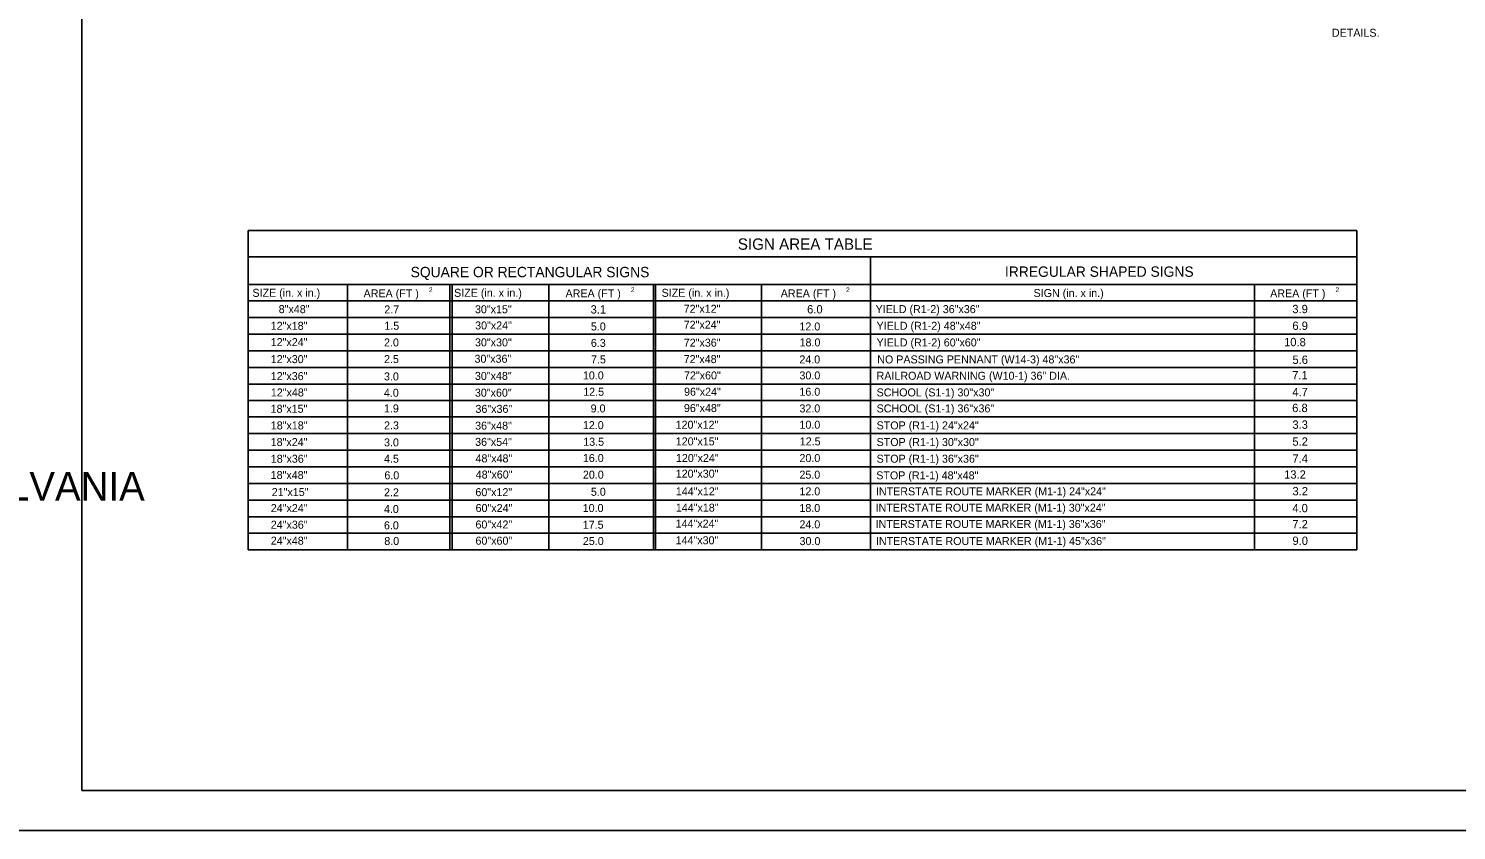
# Model space of a CAD drawing. Extents: x 644358 to 648627, y 294594 to 295782.
# Drawn here: x 645219 to 645755, y 294594 to 294894 of the extents above; entities that cross this region are included whole.
import ezdxf

# ---------------------------------------------------------------- set-up
doc = ezdxf.new("R2010")
doc.units = 0
for name, color, linetype in [('1', 7, 'Continuous'), ('2', 7, 'Continuous'), ('3', 7, 'Continuous'), ('4', 7, 'Continuous'), ('PLT-BNDY', 7, 'Continuous')]:
    doc.layers.add(name, color=color, linetype=linetype)

msp = doc.modelspace()

# ---------------------------------------------------------------- linework, layer by layer
at = {"layer": '1'}
for p, q in [((645239.31, 295172.63), (645239.31, 294608.63)), ((646025.31, 294608.63), (645239.31, 294608.63)), ((645239.31, 294608.63), (645825.31, 294608.63))]:
    msp.add_line(p, q, dxfattribs=at)
at = {"layer": '2'}
for p, q in [((645301.64, 294818.71), (645301.64, 294698.96)), ((645717.39, 294818.71), (645301.64, 294818.71)), ((645717.39, 294698.96), (645717.39, 294818.71)), ((645717.39, 294808.84), (645301.64, 294808.84)), ((645535.01, 294808.84), (645535.01, 294698.96)), ((645301.64, 294798.46), (645717.39, 294798.46)), ((645338.89, 294798.46), (645338.89, 294698.96)), ((645377.26, 294798.46), (645377.26, 294698.96)), ((645378.14, 294798.46), (645378.14, 294698.96)), ((645414.43, 294798.46), (645414.43, 294698.96)), ((645453.64, 294798.46), (645453.64, 294698.96)), ((645454.39, 294798.46), (645454.39, 294698.96)), ((645494.14, 294798.46), (645494.14, 294698.96)), ((645679.01, 294698.96), (645679.01, 294798.46)), ((645301.64, 294792.34), (645717.39, 294792.34)), ((645301.64, 294786.09), (645717.39, 294786.09)), ((645301.64, 294779.84), (645717.39, 294779.84)), ((645301.64, 294773.59), (645717.39, 294773.59)), ((645301.64, 294767.34), (645717.39, 294767.34)), ((645301.64, 294761.09), (645717.39, 294761.09)), ((645301.64, 294754.96), (645717.39, 294754.96)), ((645301.64, 294748.84), (645717.39, 294748.84)), ((645301.64, 294742.59), (645717.39, 294742.59)), ((645301.64, 294736.34), (645717.39, 294736.34)), ((645301.64, 294730.09), (645717.39, 294730.09)), ((645301.64, 294723.84), (645717.39, 294723.84)), ((645301.64, 294717.59), (645717.39, 294717.59)), ((645535.01, 294717.59), (645717.39, 294717.59)), ((645301.64, 294711.34), (645717.39, 294711.34)), ((645717.39, 294711.34), (645535.01, 294711.34)), ((645301.64, 294705.21), (645717.39, 294705.21)), ((645301.64, 294698.96), (645535.01, 294698.96)), ((645717.39, 294698.96), (645535.01, 294698.96))]:
    msp.add_line(p, q, dxfattribs=at)
at = {"layer": '4'}
for p, q in [((645356.09, 294712.84), (645356.09, 294712.84)), ((645356.09, 294706.59), (645356.09, 294706.59)), ((645356.09, 294700.34), (645356.09, 294700.34))]:
    msp.add_line(p, q, dxfattribs=at)
at = {"layer": 'PLT-BNDY'}
msp.add_lwpolyline([(645199.31, 295187.63), (646040.31, 295187.63), (646040.31, 294593.63), (645199.31, 294593.63)], close=True, dxfattribs=at)

# ---------------------------------------------------------------- texts
at = {"layer": '1'}
msp.add_text('COMMONWEALTH OF PENNSYLVANIA', height=10.7828, dxfattribs=at).set_placement((644996.9, 294717.36))
at = {"layer": '3'}
msp.add_text('DETAILS.', height=3, dxfattribs=at).set_placement((645708.03, 294891.41))
at = {"layer": '4'}
for s, height, p in [('SIGN AREA TABLE', 4.25, (645485.26, 294811.5)), ('SQUARE OR RECTANGULAR SIGNS', 3.8872, (645362.56, 294801.19)), ('IRREGULAR SHAPED SIGNS', 3.8872, (645585.41, 294801.34)), ('2', 1.8, (645369.42, 294795.6)), ('2', 1.8, (645445.15, 294795.6)), ('2', 1.8, (645525.85, 294795.6)), ('2', 1.8, (645709.36, 294795.6)), ('SIZE (in. x in.)', 3, (645303.26, 294793.84)), ('AREA (FT )', 3, (645344.93, 294793.63)), ('SIZE (in. x in.)', 3, (645378.87, 294793.84)), ('AREA (FT )', 3, (645420.66, 294793.63)), ('SIZE (in. x in.)', 3, (645456.69, 294793.84)), ('AREA (FT )', 3, (645501.36, 294793.63)), ('SIGN (in. x in.)', 3, (645596.15, 294793.76)), ('AREA (FT )', 3, (645684.87, 294793.63)), ('8"x48"', 3, (645313.11, 294787.71)), ('2.7', 3, (645352.7, 294787.6)), ('30"x15"', 3, (645386.7, 294787.67)), ('3.1', 3.125, (645430.06, 294787.55)), ('72"x12"', 3, (645464.95, 294787.85)), ('6.0', 3.125, (645511.25, 294787.6)), ('YIELD (R1-2) 36"x36" ', 3, (645536.92, 294787.72)), ('3.9', 3.125, (645693.18, 294787.71)), ('12"x18"', 3, (645310.11, 294781.46)), ('1.5', 3, (645352.73, 294781.49)), ('30"x24"', 3, (645386.76, 294781.6)), ('5.0', 3, (645430.16, 294781.22)), ('72"x24"', 3, (645464.97, 294781.88)), ('12.0', 3, (645508.36, 294781.22)), ('YIELD (R1-2) 48"x48" ', 3, (645537.29, 294781.47)), ('6.9', 3.125, (645693.21, 294781.42)), ('12"x24"', 3, (645310.11, 294775.34)), ('2.0', 3, (645352.6, 294775.22)), ('30"x30"', 3, (645386.71, 294775.25)), ('6.3', 3, (645430.16, 294775.05)), ('72"x36"', 3, (645464.99, 294775.14)), ('18.0', 3, (645508.41, 294775.23)), ('YIELD (R1-2) 60"x60" ', 3, (645537.29, 294775.22)), ('10.8', 3.125, (645690.09, 294775.3)), ('12"x30"', 3, (645310.11, 294768.96)), ('2.5', 3, (645352.6, 294768.98)), ('30"x36"', 3, (645386.53, 294769.1)), ('7.5', 3, (645430.2, 294768.85)), ('72"x48"', 3, (645464.96, 294768.97)), ('24.0', 3, (645508.32, 294768.85)), ('NO PASSING PENNANT (W14-3) 48"x36" ', 3, (645537.54, 294768.85)), ('5.6', 3.125, (645693.23, 294768.67)), ('12"x36"', 3, (645310.11, 294762.59)), ('3.0', 3, (645352.59, 294762.47)), ('30"x48"', 3, (645386.68, 294762.67)), ('10.0', 3, (645427.17, 294762.85)), ('72"x60"', 3, (645465.08, 294762.85)), ('30.0', 3, (645508.37, 294762.85)), ('RAILROAD WARNING (W10-1) 36" DIA.', 3, (645537.29, 294762.72)), ('7.1', 3.125, (645693.13, 294762.86)), ('12.5', 3, (645427.29, 294756.72)), ('96"x24"', 3, (645465.1, 294756.73)), ('16.0', 3, (645508.36, 294756.72)), ('SCHOOL (S1-1) 30"x30" ', 3, (645537.29, 294756.47)), ('4.7', 3.125, (645693.18, 294756.56)), ('12"x48"', 3, (645310.16, 294756.46)), ('4.0', 3, (645352.55, 294756.34)), ('30"x60"', 3, (645386.68, 294756.37)), ('18"x15"', 3, (645310.08, 294750.34)), ('1.9', 3, (645352.58, 294750.47)), ('36"x36"', 3, (645386.88, 294750.3)), ('9.0', 3, (645430.07, 294750.47)), ('96"x48"', 3, (645465.05, 294750.61)), ('32.0', 3, (645508.36, 294750.47)), ('SCHOOL (S1-1) 36"x36" ', 3, (645537.29, 294750.47)), ('6.8', 3.125, (645693.12, 294750.6)), ('18"x18"', 3, (645310.14, 294744.09)), ('2.3', 3, (645352.6, 294744.1)), ('36"x48"', 3, (645386.76, 294744)), ('12.0', 3, (645427.16, 294744.2)), ('120"x12"', 3, (645461.94, 294744.35)), ('10.0', 3, (645508.37, 294744.35)), ('STOP (R1-1) 24"x24" ', 3, (645537.29, 294744.1)), ('3.3', 3.125, (645693.21, 294744.33)), ('18"x24"', 3, (645310.11, 294737.84)), ('3.0', 3, (645352.6, 294737.72)), ('36"x54"', 3, (645386.76, 294737.92)), ('13.5', 3, (645427.29, 294737.95)), ('120"x15"', 3, (645461.99, 294738.1)), ('12.5', 3, (645508.49, 294738.1)), ('STOP (R1-1) 30"x30"', 3, (645537.29, 294737.85)), ('5.2', 3.125, (645693.21, 294737.97)), ('18"x36"', 3, (645310.14, 294731.59)), ('4.5', 3, (645352.6, 294731.6)), ('48"x48"', 3, (645386.91, 294731.72)), ('16.0', 3, (645427.16, 294731.85)), ('120"x24"', 3, (645462.05, 294731.86)), ('20.0', 3, (645508.37, 294731.85)), ('STOP (R1-1) 36"x36" ', 3, (645537.29, 294731.6)), ('7.4', 3.125, (645693.21, 294731.6)), ('18"x48"', 3, (645310.1, 294725.48)), ('6.0', 3, (645352.73, 294725.36)), ('48"x60"', 3, (645386.99, 294725.67)), ('20.0', 3, (645427.17, 294725.6)), ('120"x30"', 3, (645461.98, 294725.99)), ('25.0', 3, (645508.36, 294725.6)), ('STOP (R1-1) 48"x48"', 3, (645537.17, 294725.35)), ('13.2', 3.125, (645690.1, 294725.6)), ('5.0', 3, (645430.16, 294719.2)), ('144"x12"', 3, (645462.02, 294719.36)), ('12.0', 3, (645508.36, 294719.35)), ('INTERSTATE ROUTE MARKER (M1-1) 24"x24" ', 3, (645537.04, 294719.35)), ('3.2', 3.125, (645693.24, 294719.35)), ('21"x15"', 3, (645310.5, 294719.09)), ('2.2', 3, (645352.59, 294718.98)), ('60"x12"', 3, (645386.86, 294719.05)), ('24"x24"', 3, (645310.15, 294713.09)), ('4.0', 3, (645352.56, 294712.71)), ('60"x24"', 3, (645386.93, 294713.1)), ('10.0', 3, (645427.1, 294713.1)), ('144"x18"', 3, (645462.02, 294713.24)), ('18.0', 3, (645508.35, 294713.1)), ('INTERSTATE ROUTE MARKER (M1-1) 30"x24" ', 3, (645536.92, 294713.22)), ('4.0', 3.125, (645693.19, 294713.01)), ('24"x36"', 3, (645310.15, 294706.84)), ('6.0', 3, (645352.57, 294706.59)), ('60"x42"', 3, (645386.89, 294706.92)), ('17.5', 3, (645427.11, 294706.82)), ('144"x24"', 3, (645461.93, 294707.24)), ('24.0', 3, (645508.37, 294706.97)), ('INTERSTATE ROUTE MARKER (M1-1) 36"x36" ', 3, (645536.92, 294707.1)), ('7.2', 3.125, (645693.18, 294706.97)), ('24"x48"', 3, (645310.14, 294700.85)), ('8.0', 3, (645352.7, 294700.74)), ('60"x60"', 3, (645386.89, 294700.85)), ('25.0', 3, (645427.16, 294700.72)), ('144"x30"', 3, (645461.93, 294700.99)), ('30.0', 3, (645508.41, 294700.69)), ('INTERSTATE ROUTE MARKER (M1-1) 45"x36" ', 3, (645537.04, 294700.72)), ('9.0', 3.125, (645693.23, 294700.76))]:
    msp.add_text(s, height=height, dxfattribs=at).set_placement(p)

doc.saveas('drawing.dxf')
